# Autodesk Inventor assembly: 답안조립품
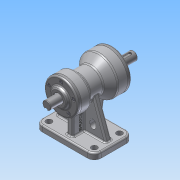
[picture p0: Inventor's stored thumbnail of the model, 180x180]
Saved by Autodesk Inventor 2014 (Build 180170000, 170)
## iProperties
Created: 2015-08
Part Number: 답안조립품
Document SubType Name: Assembly
Designer: SDA16
Author: SDA16
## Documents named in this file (10)
- C:\Users\SDA16\Desktop\450805V1016\답안조립품.iam
- C:\Users\SDA16\Desktop\450805V1016\1-본체.ipt
- C:\Users\SDA16\Desktop\450805V1016\베어링 6203.ipt
- C:\Users\SDA16\Desktop\450805V1016\뒤커버.ipt
- C:\Users\SDA16\Desktop\450805V1016\M4x0.5.ipt
- C:\Users\SDA16\Desktop\450805V1016\축.ipt
- C:\Users\SDA16\Desktop\450805V1016\베어링 6205.ipt
- C:\Users\SDA16\Desktop\450805V1016\앞커버.ipt
- C:\Users\SDA16\Desktop\450805V1016\오일실 .ipt
- 오일실 .ipt
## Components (11 placed, 2 different names)
1. 1-본체:1
2. M4x0.5:1
3. M4x0.5:2
4. M4x0.5:3
5. M4x0.5:4
6. M4x0.5:5
7. M4x0.5:6
8. M4x0.5:7
9. M4x0.5:8
10. M4x0.5:9
11. M4x0.5:10
